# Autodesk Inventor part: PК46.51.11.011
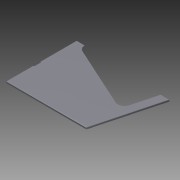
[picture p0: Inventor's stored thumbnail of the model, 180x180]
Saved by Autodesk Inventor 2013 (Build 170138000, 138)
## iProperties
Shininess: 64.0
Length Units: 11269
Angle Units: 11279
Time Units: 11290
Mass Units: 11283
Length Display Precision: 3
Angle Display Precision: 2
Compacted: True
Part Number: PК46.51.11.011
Document SubType Name: Листовой материал
Created: 2005-02
Material: Steel, Mild
Designer: =<Author>
Manufacturer: Standard
Standards Organization: Custom
Description: Bottom Plate
Density: 7.86 g/cm^3
Flat Pattern Width: 52.8524 cm
Flat Pattern Length: 73.9766 cm
Flat Pattern Area: 3909.84 cm^2
Sheet Metal Rule: По умолчанию
Mass: 4165.48 g
Surface Area: 5352.94 cm^2
Volume: 529.959 cm^3
Density: 0.0
Volumn: 0.0
Area: 0.0
PropertySet Name: Model Information
Control State: 0
Master: False
Checked Out: False
Checked Out Date: 2008-10-15
Last Check In Date: 2008-10-15
Толщина: 2.000 mm
Радиус_гибки: 2.000 mm
Ширина_просечки: 2.000 mm
Глубина_просечки: 1.000 mm
Размер_высечки: 8.000 mm
Минимальный_остаток: 4.000 mm
Радиус_перехода: 2.000 mm
JacobiRadiusSize: 2.000 mm
GapSize: 2.000 mm
d0: 595.000 mm
d1: 520.000 mm
d2: 62.000 mm
d3: 62.000 mm
d4: 128.000 mm
d5: 100.000 mm
d6: 50.000 mm
d7: 2.000 mm
d8: 2.000 mm
d9: 1.000 mm
d10: 4.000 mm
d11: 2.000 mm
d12: 10.000 mm
d13: 90.00 deg
d14: 2.000 mm
d15: 2.000 mm
d16: 1.000 mm
d17: 4.000 mm
d18: 2.000 mm
d19: 10.000 mm
d20: 90.00 deg
d21: 2.000 mm
d22: 2.000 mm
d23: 1.000 mm
d24: 4.000 mm
d25: 2.000 mm
d26: 10.000 mm
d27: 90.00 deg
d28: 2.000 mm
d29: 8.000 mm
d30: 2.000 mm
d31: 0.100 mm
d32: 0.000 mm
d33: 8.000 mm
d34: 2.000 mm
d35: 0.100 mm
d36: 0.000 mm
d37: 50.000 mm
d38: 200.000 mm
d39: 7.000 mm
d41: 0.00 deg
d54: 485.000 mm
d55: 205.000 mm
Author: PVitaliy
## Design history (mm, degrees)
node "Грань1"
node "Фланец1"
node "Фланец2"
node "Фланец3"
feature "УглСтык1" dims "d29" = 8 (= Размер_высечки), "d30" = 2 (= Радиус_гибки), "d31" = 0.1, "d32" = 0, "Толщина" = 2
feature "УглСтык2" dims "d33" = 8 (= Размер_высечки), "d34" = 2 (= Радиус_гибки), "d35" = 0.1, "d36" = 0, "Толщина" = 2
feature "Вырез1" dims "d40" = 2 (= Толщина), angle "d41" = 0 deg
body "Solid1"
sketch "Эскиз1"
  geometry: L1 (0, 0)-(595, 0); L2 (0, 0)-(0, 520); L3 (0, 520)-(62, 520); L4 (723, 485)-(658.877, 485); L5 (595, 0)-(723, 485); L6 (658.877, 485)-(610.644, 302.241); L7 (541.582, 269.494)-(91.283, 474.494); A1 r 50 centre (112, 520) between (62, 520) and (91.283, 474.494); A2 r 50 centre (562.299, 315) between (541.582, 269.494) and (610.644, 302.241)
  constraints: 14 end point, 4 point on circle, 3 tangent, 2 centre point, 2 parallel, 2 perpendicular, 1 horizontal, 1 point on line, 1 other
  dimensions: "d0" = 595 distance of L1.start L1.end; "d1" = 520 distance of L1.start L2.end; "d2" = 62 distance of L2.end L3.end; "d3" = 62 distance between parallel lines of L5 L6; "d4" = 128 horizontal distance of L1.end L4.start; "d5" = 100 diameter of A1; "d6" = 50 radius of A2; "d54" = 485 distance between parallel lines of L4 L1; "d55" = 205 distance from line of A2.centre L3
feature "Пластина1" dims "Толщина" = 2
sketch "Эскиз2"
  geometry: L1 through (-250.803, 0) direction (-1, 0); L2 (-501.606, 0)-(-501.606, -10); L3 (-501.606, -10)-(0, -10); L4 through (0, -5) direction (-1.51e-17, 1)
  constraints: 6 end point, 1 horizontal, 1 perpendicular, 1 vertical
feature "Пластина2" dims "d8" = 2 (= Ширина_просечки), "d10" = 4 (= Минимальный_остаток), "d12" = 10, angle "d13" = 90 deg, "d14" = 2 (= Радиус_гибки), "Толщина" = 2
feature "Изгиб1" dims "d8" = 2 (= Ширина_просечки), "d9" = 1 (= Глубина_просечки), "d10" = 4 (= Минимальный_остаток), "d11" = 2 (= Радиус_гибки), "d12" = 10, angle "d13" = 90 deg, "d14" = 2 (= Радиус_гибки), "Толщина" = 2, "Зазор_стыка" = 0.01
sketch "Эскиз3"
  geometry: L1 through (-295.432, 0) direction (-1, -3.26e-33); L2 (-590.863, 0)-(-590.863, -10); L3 (-590.863, -10)-(0, -10); L4 through (0, -5) direction (0, 1)
  constraints: 6 end point, 1 horizontal, 1 perpendicular, 1 vertical
feature "Пластина3" dims "d15" = 2 (= Ширина_просечки), "d17" = 4 (= Минимальный_остаток), "d19" = 10, angle "d20" = 90 deg, "d21" = 2 (= Радиус_гибки), "Толщина" = 2
feature "Изгиб2" dims "d15" = 2 (= Ширина_просечки), "d16" = 1 (= Глубина_просечки), "d17" = 4 (= Минимальный_остаток), "d18" = 2 (= Радиус_гибки), "d19" = 10, angle "d20" = 90 deg, "d21" = 2 (= Радиус_гибки), "Толщина" = 2, "Зазор_стыка" = 0.01
sketch "Эскиз4"
  geometry: L1 through (-258, 0) direction (-1, 8.54e-33); L2 (-516, 0)-(-516, -10); L3 (-516, -10)-(0, -10); L4 through (0, -5) direction (-1.12e-32, 1)
  constraints: 6 end point, 1 horizontal, 1 perpendicular, 1 vertical
feature "Пластина4" dims "d22" = 2 (= Ширина_просечки), "d24" = 4 (= Минимальный_остаток), "d26" = 10, angle "d27" = 90 deg, "d28" = 2 (= Радиус_гибки), "Толщина" = 2
feature "Изгиб3" dims "d22" = 2 (= Ширина_просечки), "d23" = 1 (= Глубина_просечки), "d24" = 4 (= Минимальный_остаток), "d25" = 2 (= Радиус_гибки), "d26" = 10, angle "d27" = 90 deg, "d28" = 2 (= Радиус_гибки), "Толщина" = 2, "Зазор_стыка" = 0.01
sketch "Эскиз5"
  geometry: L1 (-654.877, 35)-(-654.877, -481) reference; L2 (-658.877, -482.9)-(-658.877, 35) reference; L3 (-658.877, -285)-(-649.877, -285); L4 (-649.877, -285)-(-649.877, -235); L5 (-649.877, -235)-(-658.877, -235); L6 (-65.521, -485)-(-656.777, -485) reference; L7 (-656.877, 35)-(-656.877, -482.9) reference
  constraints: 6 end point, 2 perpendicular, 2 point on line, 1 parallel
  dimensions: "d37" = 50 distance of L3.end L4.end; "d38" = 200 distance between parallel lines of L3 L6; "d39" = 7 distance between parallel lines of L7 L4
node "Развертка"
feature "FlatPatternExtrusion2" dims "d0" = 2 (derived)
other parameters: "Радиус_гибки" = 2 (= Толщина), "Ширина_просечки" = 2 (= Толщина), "Глубина_просечки" = 1 (= 0.5 x Толщина), "Размер_высечки" = 8 (= 4 x Толщина), "Минимальный_остаток" = 4 (= 2 x Толщина), "Радиус_перехода" = 2 (= Радиус_гибки), "d7" = 2 (= Радиус_гибки), "JacobiRadiusSize" = 2 (= Толщина), "GapSize" = 2 (= Толщина)
